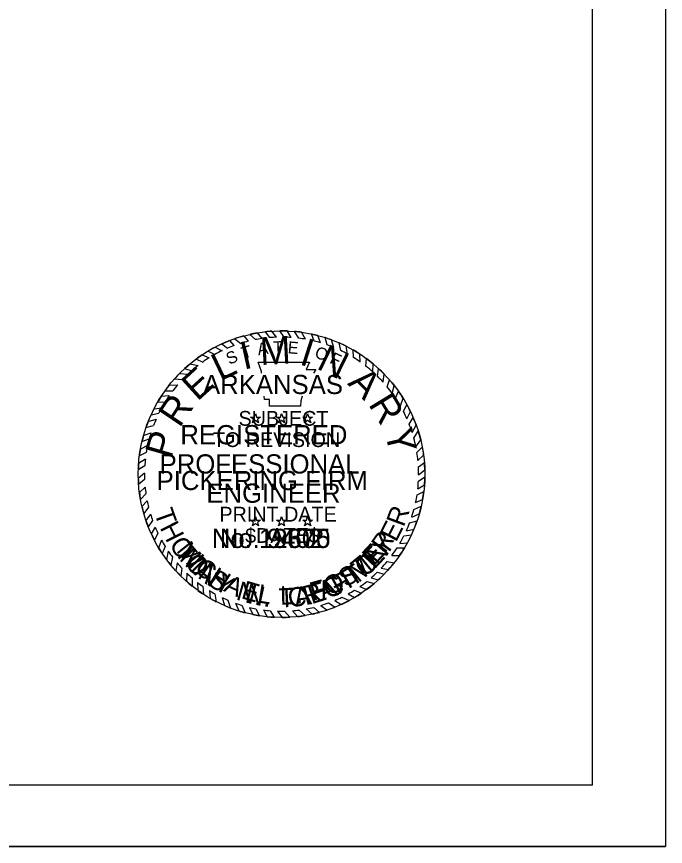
# Model space of a CAD drawing. Extents: x 79818 to 83933, y 50884 to 53307.
# Drawn here: x 83511 to 83933, y 51174 to 51714 of the extents above; entities that cross this region are included whole.
import ezdxf

# ---------------------------------------------------------------- set-up
doc = ezdxf.new("R2010")
doc.units = 0
for name, color, linetype in [('R_Border', 7, 'Continuous'), ('R_No Plot', 7, 'Continuous'), ('STAMP_PE_CRAFTON', 7, 'Continuous'), ('STAMP_PE_FOSTER', 7, 'Continuous'), ('STAMP_PE_SEAL-INFO', 7, 'Continuous'), ('STAMP_PE_TAEGTMEYER', 7, 'Continuous'), ('STAMP_PE_TXT', 7, 'Continuous'), ('STAMP_PRELIMINARY', 7, 'Continuous')]:
    doc.layers.add(name, color=color, linetype=linetype)

msp = doc.modelspace()

# ---------------------------------------------------------------- linework, layer by layer
at = {"layer": 'R_Border'}
for q in [(83885.4, 53268.52), (80723.6, 51213.92)]:
    msp.add_line((83885.4, 51213.92), q, dxfattribs=at)
at = {"layer": 'R_No Plot'}
msp.add_line((80599.59, 51174.13), (83932.93, 51174.13), dxfattribs=at)
msp.add_lwpolyline([(80599.53, 53307.47), (83932.93, 53307.47), (83932.93, 51174.09), (80599.53, 51174.09)], close=True, dxfattribs=at)
at = {"layer": 'STAMP_PE_SEAL-INFO'}
for p, q in [((83667.44, 51508.13), (83670.43, 51504.46)), ((83672.6, 51508.86), (83675.41, 51505.04)), ((83679.95, 51505.32), (83676.83, 51509.25)), ((83684.93, 51505.36), (83682.15, 51509.47)), ((83689.51, 51505.16), (83686.93, 51509.4)), ((83694.57, 51504.66), (83691.65, 51509.09)), ((83698.83, 51504.01), (83696.25, 51508.56)), ((83649.35, 51503.1), (83652.3, 51499.84)), ((83652.83, 51504.37), (83656.64, 51501.32)), ((83658.74, 51506.2), (83661.62, 51502.72)), ((83662.62, 51507.16), (83666.18, 51503.73)), ((83704.45, 51502.82), (83702.71, 51507.42)), ((83708.47, 51501.74), (83706.87, 51506.43)), ((83712.98, 51500.27), (83711.57, 51505.06)), ((83717.17, 51498.67), (83715.72, 51503.63)), ((83639.97, 51498.82), (83644.6, 51496.57)), ((83644.28, 51500.94), (83648.17, 51498.19)), ((83721.78, 51496.62), (83720.75, 51501.59)), ((83726.24, 51494.32), (83725.37, 51499.41)), ((83730.11, 51492.06), (83729.72, 51497.06)), ((83631.62, 51493.88), (83636.04, 51491.86)), ((83635.49, 51496.32), (83639.81, 51494.09)), ((83734.46, 51489.19), (83734.15, 51494.34)), ((83738.06, 51486.52), (83738.41, 51491.4)), ((83623.65, 51487.94), (83628.94, 51486.93)), ((83627.41, 51491.21), (83631.97, 51489.16)), ((83667.97, 51489.16), (83701.41, 51489.16)), ((83669.18, 51486.08), (83667.97, 51489.16)), ((83670.22, 51483.11), (83669.18, 51486.08)), ((83701.41, 51489.16), (83699.16, 51484.24)), ((83742.53, 51482.8), (83742.73, 51488.03)), ((83616.85, 51481.7), (83622.3, 51481.29)), ((83620.21, 51484.94), (83624.8, 51483.55)), ((83670.29, 51481.96), (83670.22, 51483.11)), ((83699.16, 51484.24), (83705.48, 51484.24)), ((83705.48, 51484.24), (83704.03, 51481.96)), ((83745.66, 51479.88), (83746.35, 51484.86)), ((83749.25, 51476.14), (83749.91, 51481.4)), ((83613.63, 51478.26), (83618.84, 51477.88)), ((83751.98, 51472.98), (83753.35, 51477.69)), ((83607.39, 51470.45), (83612.44, 51470.4)), ((83610.17, 51474.15), (83615.66, 51474.37)), ((83755.22, 51468.81), (83756.58, 51473.8)), ((83757.42, 51465.66), (83759.2, 51470.29)), ((83605.04, 51467.01), (83610.2, 51467.35)), ((83672.2, 51464.87), (83671.94, 51467.05)), ((83675.35, 51464.87), (83672.2, 51464.87)), ((83675.35, 51460.57), (83675.35, 51464.87)), ((83696.58, 51467.05), (83695.8, 51463.95)), ((83760.5, 51460.68), (83762.33, 51465.59)), ((83600.27, 51458.77), (83605.25, 51459.42)), ((83602.58, 51463), (83607.47, 51463.2)), ((83695.64, 51460.57), (83675.35, 51460.57)), ((83695.8, 51463.95), (83695.64, 51460.57)), ((83762.5, 51457.02), (83764.76, 51461.46)), ((83598.39, 51454.88), (83603.42, 51455.92)), ((83764.81, 51452.18), (83767.07, 51457.02)), ((83596.55, 51450.55), (83601.59, 51452.02)), ((83766.21, 51448.81), (83768.85, 51453.14)), ((83768.16, 51443.32), (83770.87, 51448.06)), ((83593.48, 51441.46), (83598.26, 51443.15)), ((83595.05, 51446.49), (83599.89, 51447.85)), ((83769.24, 51439.67), (83772.18, 51444.19)), ((83592.44, 51437.39), (83597.14, 51439.31)), ((83770.57, 51434.08), (83773.76, 51438.55)), ((83596.08, 51434.92), (83591.43, 51432.43)), ((83771.26, 51430.28), (83774.79, 51433.81)), ((83595.22, 51430.34), (83590.77, 51428.11)), ((83771.92, 51425.19), (83775.65, 51428.55)), ((83594.27, 51421.73), (83590.06, 51419.16)), ((83594.63, 51425.98), (83590.27, 51423.17)), ((83772.24, 51421.01), (83776.15, 51423.93)), ((83594.1, 51416.8), (83590.05, 51413.44)), ((83772.37, 51415.83), (83776.42, 51419.05)), ((83594.17, 51412.73), (83590.26, 51409.48)), ((83772.26, 51411.78), (83776.45, 51414.55)), ((83594.5, 51407.77), (83590.79, 51404.21)), ((83771.36, 51402.83), (83775.79, 51405.03)), ((83771.86, 51406.72), (83776.2, 51409.28)), ((83595.02, 51403.48), (83591.48, 51399.75)), ((83770.45, 51397.83), (83775, 51399.79)), ((83595.81, 51398.89), (83592.41, 51395.22)), ((83596.74, 51394.7), (83593.62, 51390.55)), ((83769.37, 51393.31), (83774.09, 51395.33)), ((83597.98, 51390.23), (83595.03, 51386.05)), ((83767.9, 51388.37), (83772.8, 51390.38)), ((83599.39, 51386), (83596.57, 51381.88)), ((83766.55, 51384.57), (83771.38, 51385.88)), ((83601.05, 51381.74), (83598.44, 51377.51)), ((83602.77, 51377.9), (83600.49, 51373.3)), ((83764.41, 51379.43), (83769.29, 51380.39)), ((83605.12, 51373.32), (83603.21, 51368.42)), ((83762.8, 51376.07), (83767.68, 51376.75)), ((83607.48, 51369.28), (83605.64, 51364.58)), ((83758.36, 51368.28), (83763.14, 51368.21)), ((83760.08, 51371.08), (83765.09, 51371.62)), ((83609.5, 51366.17), (83608.4, 51360.65)), ((83612.31, 51362.26), (83611.29, 51356.96)), ((83754.97, 51363.33), (83760.01, 51363.36)), ((83615.35, 51358.49), (83614.48, 51353.29)), ((83751.89, 51359.39), (83756.5, 51358.6)), ((83618.37, 51355.11), (83617.75, 51349.89)), ((83621.6, 51351.86), (83621.3, 51346.57)), ((83745.51, 51352.47), (83749.92, 51351.09)), ((83748.06, 51355.06), (83752.83, 51354.21)), ((83625.04, 51348.73), (83625.01, 51343.44)), ((83628.64, 51345.79), (83628.83, 51340.54)), ((83738.74, 51346.5), (83743.42, 51345.05)), ((83741.45, 51348.74), (83746.16, 51347.46)), ((83632.03, 51343.29), (83632.39, 51338.11)), ((83636.3, 51340.47), (83636.9, 51335.35)), ((83730.7, 51340.8), (83735.19, 51338.84)), ((83734.14, 51343.07), (83738.52, 51341.18)), ((83639.8, 51338.41), (83640.71, 51333.28)), ((83644.61, 51335.91), (83646.18, 51330.7)), ((83722.48, 51336.21), (83727.31, 51334.1)), ((83726.55, 51338.34), (83730.72, 51336.02)), ((83648.33, 51334.23), (83650.06, 51329.12)), ((83653.26, 51332.3), (83655.35, 51327.29)), ((83657.36, 51330.95), (83659.62, 51326.06)), ((83662.44, 51329.57), (83664.56, 51324.91)), ((83704.17, 51329.6), (83707.95, 51326.35)), ((83708.76, 51330.84), (83712.93, 51327.87)), ((83713.69, 51332.47), (83718.12, 51329.79)), ((83717.88, 51334.12), (83722.12, 51331.51)), ((83666.41, 51328.71), (83668.88, 51324.13)), ((83671.41, 51327.9), (83673.81, 51323.5)), ((83675.78, 51327.42), (83678.52, 51323.14)), ((83680.63, 51327.15), (83683.65, 51323.02)), ((83685.22, 51327.13), (83688.66, 51323.18)), ((83690.41, 51327.4), (83693.67, 51323.6)), ((83694.79, 51327.86), (83698.52, 51324.28)), ((83699.24, 51328.56), (83703.13, 51325.17))]:
    msp.add_line(p, q, dxfattribs=at)
for radius, start, end in [(93.23, 99.7525, 102.7765), (93.23, 93.9381, 96.5517), (93.23, 87.7298, 90.6707), (93.23, 81.9732, 84.8236), (93.23, 111.3124, 114.7026), (93.23, 105.2339, 109.0352), (89.14, 104.0352, 107.3615), (89.14, 98.258, 101.0329), (89.14, 92.1102, 95.0367), (89.14, 85.9628, 88.9097), (89.14, 79.9264, 82.696), (93.23, 75.3125, 77.9426), (89.14, 73.5575, 76.2314), (93.23, 69.6061, 72.3058), (93.23, 117.6544, 120.8099), (89.14, 110.3086, 113.1659), (89.14, 67.6248, 70.504), (93.23, 63.1329, 66.2704), (93.23, 56.9003, 60.0942), (93.23, 123.6199, 126.5906), (89.14, 121.9746, 125.11), (89.14, 115.6869, 119.1583), (89.14, 61.1558, 64.3784), (89.14, 54.9238, 58.2702), (93.23, 50.3492, 53.7159), (93.23, 129.7326, 132.5376), (89.14, 127.5297, 130.9683), (89.14, 48.3016, 52.0395), (93.23, 135.4021, 138.3031), (89.14, 133.1331, 136.2562), (93.23, 44.3405, 47.3929), (89.14, 42.2212, 45.5512), (93.23, 38.1247, 41.2316), (93.23, 141.6056, 144.4486), (89.14, 139.301, 142.5873), (89.14, 36.135, 39.5311), (93.23, 31.9614, 35.4294), (93.23, 147.0072, 149.899), (89.14, 145.0197, 148.2104), (89.14, 29.9032, 33.6645), (89.14, 151.0315, 153.573), (93.23, 25.9391, 29.0125), (93.23, 152.864, 155.5189), (89.14, 23.7732, 27.2211), (93.23, 158.4077, 161.0701), (89.14, 156.3402, 159.2319), (89.14, 17.6802, 21.4251), (93.23, 19.9538, 23.3141), (89.14, 162.4331, 165.0013), (93.23, 13.8421, 17.4447), (93.23, 164.3068, 166.894), (89.14, 11.5444, 15.2364), (93.23, 170.0003, 172.6878), (89.14, 167.9048, 170.9039), (93.23, 7.5852, 10.8621), (89.14, 5.7599, 9.0606), (93.23, 175.7409, 178.2066), (89.14, 173.73, 176.4734), (93.23, 1.7215, 4.7268), (89.14, 179.6454, 182.2633), (89.14, 359.7329, 3.0639), (93.23, 181.7251, 184.1626), (89.14, 353.8632, 357.1274), (93.23, 355.7156, 358.9569), (89.14, 185.4539, 188.234), (93.23, 349.8305, 353.0885), (93.23, 187.4204, 190.1927), (89.14, 348.0778, 351.3435), (93.23, 193.0369, 195.9973), (89.14, 191.2274, 193.9858), (93.23, 343.8925, 347.035), (89.14, 196.9675, 199.8353), (89.14, 341.777, 345.0925), (93.23, 198.8967, 201.6281), (89.14, 335.6038, 339.1858), (93.23, 337.3837, 340.9933), (89.14, 202.7761, 205.4791), (93.23, 204.5479, 207.4328), (89.14, 208.7883, 211.7934), (89.14, 329.5549, 333.2076), (93.23, 331.4037, 334.9332), (93.23, 210.8636, 213.6571), (89.14, 323.5851, 327.4407), (93.23, 325.4405, 328.9872), (89.14, 214.1838, 217.2747), (93.23, 216.6115, 219.491), (89.14, 220.3909, 223.3056), (89.14, 316.6531, 320.3711), (93.23, 318.2846, 321.8043), (93.23, 222.48, 225.3801), (89.14, 226.2494, 229.2407), (89.14, 310.7744, 314.3161), (93.23, 312.4518, 315.6633), (93.23, 228.3665, 231.348), (89.14, 232.229, 234.9336), (89.14, 304.823, 308.5143), (93.23, 234.295, 236.9452), (89.14, 238.2223, 240.8353), (89.14, 299.0768, 302.1724), (93.23, 306.3721, 310.208), (93.23, 240.1977, 242.8613), (89.14, 244.3204, 246.9486), (89.14, 292.8745, 296.1185), (93.23, 300.621, 303.8703), (93.23, 246.576, 249.1558), (89.14, 250.3491, 253.1216), (89.14, 256.505, 259.1192), (89.14, 280.3459, 283.5814), (89.14, 286.6423, 289.9783), (93.23, 288.5709, 291.9733), (93.23, 294.6481, 298.2166), (93.23, 252.5967, 255.3252), (93.23, 258.4433, 261.1398), (89.14, 262.3783, 265.2012), (89.14, 268.3215, 271.277), (89.14, 274.6157, 277.4486), (93.23, 276.4239, 279.4357), (93.23, 282.3199, 285.3702), (93.23, 264.1978, 267.1009), (93.23, 270.2548, 273.3361)]:
    msp.add_arc((83683.24, 51416.25), radius, start, end, dxfattribs=at)
at = {"layer": 'STAMP_PE_TXT'}
for p, q in [((83665.5, 51453.4), (83666.26, 51455.73)), ((83666.26, 51455.73), (83667.01, 51453.4)), ((83682.48, 51453.4), (83683.24, 51455.73)), ((83683.24, 51455.73), (83683.99, 51453.4)), ((83699.46, 51453.4), (83700.22, 51455.73)), ((83700.22, 51455.73), (83700.97, 51453.4)), ((83665.03, 51451.96), (83663.05, 51453.4)), ((83663.05, 51453.4), (83665.5, 51453.4)), ((83664.27, 51449.63), (83665.03, 51451.96)), ((83666.26, 51451.07), (83664.27, 51449.63)), ((83668.24, 51449.63), (83666.26, 51451.07)), ((83667.01, 51453.4), (83669.47, 51453.4)), ((83669.47, 51453.4), (83667.48, 51451.96)), ((83667.48, 51451.96), (83668.24, 51449.63)), ((83682.01, 51451.96), (83680.03, 51453.4)), ((83680.03, 51453.4), (83682.48, 51453.4)), ((83681.25, 51449.63), (83682.01, 51451.96)), ((83683.24, 51451.07), (83681.25, 51449.63)), ((83685.22, 51449.63), (83683.24, 51451.07)), ((83683.99, 51453.4), (83686.45, 51453.4)), ((83686.45, 51453.4), (83684.46, 51451.96)), ((83684.46, 51451.96), (83685.22, 51449.63)), ((83698.99, 51451.96), (83697.01, 51453.4)), ((83697.01, 51453.4), (83699.46, 51453.4)), ((83698.23, 51449.63), (83698.99, 51451.96)), ((83700.22, 51451.07), (83698.23, 51449.63)), ((83702.2, 51449.63), (83700.22, 51451.07)), ((83700.97, 51453.4), (83703.43, 51453.4)), ((83703.43, 51453.4), (83701.44, 51451.96)), ((83701.44, 51451.96), (83702.2, 51449.63)), ((83665.03, 51384.89), (83663.05, 51386.33)), ((83663.05, 51386.33), (83665.5, 51386.33)), ((83664.27, 51382.56), (83665.03, 51384.89)), ((83666.26, 51384), (83664.27, 51382.56)), ((83665.5, 51386.33), (83666.26, 51388.66)), ((83666.26, 51388.66), (83667.01, 51386.33)), ((83668.24, 51382.56), (83666.26, 51384)), ((83667.01, 51386.33), (83669.47, 51386.33)), ((83669.47, 51386.33), (83667.48, 51384.89)), ((83667.48, 51384.89), (83668.24, 51382.56)), ((83682.01, 51384.89), (83680.03, 51386.33)), ((83680.03, 51386.33), (83682.48, 51386.33)), ((83681.25, 51382.56), (83682.01, 51384.89)), ((83683.24, 51384), (83681.25, 51382.56)), ((83682.48, 51386.33), (83683.24, 51388.66)), ((83683.24, 51388.66), (83683.99, 51386.33)), ((83685.22, 51382.56), (83683.24, 51384)), ((83683.99, 51386.33), (83686.45, 51386.33)), ((83686.45, 51386.33), (83684.46, 51384.89)), ((83684.46, 51384.89), (83685.22, 51382.56)), ((83698.99, 51384.89), (83697.01, 51386.33)), ((83697.01, 51386.33), (83699.46, 51386.33)), ((83698.23, 51382.56), (83698.99, 51384.89)), ((83700.22, 51384), (83698.23, 51382.56)), ((83699.46, 51386.33), (83700.22, 51388.66)), ((83700.22, 51388.66), (83700.97, 51386.33)), ((83702.2, 51382.56), (83700.22, 51384)), ((83700.97, 51386.33), (83703.43, 51386.33)), ((83703.43, 51386.33), (83701.44, 51384.89)), ((83701.44, 51384.89), (83702.2, 51382.56))]:
    msp.add_line(p, q, dxfattribs=at)
at = {"layer": 'STAMP_PRELIMINARY'}
msp.add_circle((83683.24, 51416.25), 93.23, dxfattribs=at)

# ---------------------------------------------------------------- texts
at = {"layer": 'STAMP_PE_CRAFTON'}
msp.add_text('No. 12370', height=12.5, dxfattribs=at).set_placement((83637.86, 51368.22))
for s, rotation, p in [('T', 310.7442, (83612.9, 51365.22)), ('N', 49.2411, (83746.06, 51356.47)), ('O', 317.6422, (83619.57, 51357.11)), ('O', 41.8391, (83737.59, 51348.65)), ('N', 324.4537, (83628.03, 51349.26)), ('T', 34.1136, (83729, 51342.63)), ('Y', 331.1686, (83638.36, 51342.1)), ('F', 28.7821, (83719.85, 51337.54)), ('A', 20.5125, (83710.04, 51333.8)), ('N', 347.4752, (83658.9, 51332.94)), ('C', 6.0117, (83687.95, 51329.66)), ('R', 14.8189, (83698.91, 51330.81)), ('.', 356.8926, (83671.2, 51330.17))]:
    msp.add_text(s, height=12.5, rotation=rotation, dxfattribs=at).set_placement(p)
at = {"layer": 'STAMP_PE_FOSTER'}
msp.add_text('No. 9402', height=12.5, dxfattribs=at).set_placement((83643.09, 51368.22))
for s, rotation, p in [('R', 54.5031, (83750.48, 51364.36)), ('M', 308.339, (83614.4, 51366.47)), ('E', 46.9613, (83743.24, 51356.15)), ('I', 314.1842, (83622.37, 51357.09)), ('T', 39.4194, (83734.66, 51348.65)), ('C', 319.8733, (83625.91, 51353.56)), ('S', 31.7234, (83725.14, 51342.37)), ('H', 327.7235, (83635.21, 51346.19)), ('O', 23.719, (83714.03, 51337.07)), ('A', 335.7276, (83645.01, 51340.38)), ('E', 343.5779, (83656.39, 51335.67)), ('F', 15.8691, (83703.59, 51333.79)), ('L', 350.8115, (83666.98, 51332.9)), ('L', 1.2666, (83682.37, 51331.33)), ('.', 6.8035, (83692.84, 51331.91))]:
    msp.add_text(s, height=12, rotation=rotation, dxfattribs=at).set_placement(p)
at = {"layer": 'STAMP_PE_TAEGTMEYER'}
for s, rotation, p in [('T', 289.646, (83600.18, 51391.35)), ('R', 69.57, (83762.69, 51381.39)), ('H', 296.7339, (83603.78, 51381.5)), ('E', 63.0984, (83757.7, 51371.57)), ('Y', 53.9986, (83751.01, 51362.17)), ('O', 303.7708, (83609.71, 51370.42)), ('M', 314.2033, (83616.26, 51360.91)), ('E', 46.8094, (83743.62, 51354.02)), ('M', 39.3, (83733.22, 51345.23)), ('A', 321.0594, (83625.87, 51351.27)), ('S', 327.8239, (83634.14, 51344.83)), ('T', 31.466, (83724.24, 51339.79)), ('N', 344.2727, (83653.1, 51334.76)), ('E', 17.6836, (83702.74, 51331.56)), ('G', 23.3052, (83713.23, 51334.86)), ('T', 3.0061, (83681.88, 51329.45)), ('A', 8.9826, (83692.35, 51330)), ('.', 350.6464, (83665.23, 51331.44))]:
    msp.add_text(s, height=12.5, rotation=rotation, dxfattribs=at).set_placement(p)
msp.add_text('No. 19605', height=12.5, dxfattribs=at).set_placement((83637.86, 51368.22))
at = {"layer": 'STAMP_PE_TXT'}
for s, rotation, p in [('T', 1.8248, (83677.94, 51494.83)), ('E', 355.2002, (83687.04, 51494.91)), ('T', 16.311, (83658.45, 51491.01)), ('A', 9.0679, (83668.08, 51493.53)), ('O', 342.2506, (83704.31, 51492.15)), ('S', 23.5541, (83649.22, 51487.28)), ('F', 335.0075, (83713.96, 51488.77))]:
    msp.add_text(s, height=7.81, rotation=rotation, dxfattribs=at).set_placement(p)
for s, p in [('ARKANSAS', (83632.16, 51468.35)), ('REGISTERED', (83617.4, 51435.66)), ('PROFESSIONAL', (83603.92, 51416.64)), ('ENGINEER', (83634.33, 51397.63))]:
    msp.add_text(s, height=12.5, dxfattribs=at).set_placement(p)
at = {"layer": 'STAMP_PRELIMINARY'}
for s, rotation, p in [('I', 12.5248, (83658.61, 51484.11)), ('M', 3.1074, (83669.59, 51487.2)), ('I', 342.3164, (83694.27, 51487.88)), ('N', 333.9382, (83705.35, 51485.14)), ('L', 25.513, (83643.32, 51476.52)), ('E', 42.3578, (83628.5, 51463.21)), ('A', 315.6579, (83725.68, 51474.88)), ('R', 56.2292, (83616.94, 51445.88)), ('R', 301.3831, (83739.36, 51461.74)), ('P', 73.913, (83611.45, 51425.65)), ('Y', 283.2593, (83750.26, 51443.88))]:
    msp.add_text(s, height=18, rotation=rotation, dxfattribs=at).set_placement(p)
for s, height, p in [('SUBJECT', 9.6, (83655.24, 51447.74)), ('TO REVISION', 9.6, (83638.59, 51433.89)), ('PICKERING FIRM', 12.5, (83601.97, 51405.88)), ('PRINT DATE', 9.6, (83642.81, 51385.4)), ('$DATE$', 9.6, (83659.58, 51371.55))]:
    msp.add_text(s, height=height, dxfattribs=at).set_placement(p)

doc.saveas('drawing.dxf')
